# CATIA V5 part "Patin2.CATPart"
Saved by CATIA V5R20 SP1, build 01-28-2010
Part number: Patin2
Bounding box of the stored display mesh (mm): x 5 to 20, y -5.97 to 52.792, z 16.039 to 116.99
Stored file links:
  J:\ACHTUNG2\Patin2.CATPart
  J:\ACHTUNG2\cmilovidof.CATProduct
  J:\ACHTUNG\IAO non optimisé fini et qui marche à rendre\Patin2.CATPart
  J:\ACHTUNG2\Equerre6.CATPart
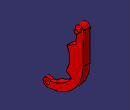
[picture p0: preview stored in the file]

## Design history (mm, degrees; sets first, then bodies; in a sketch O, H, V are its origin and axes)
External parameters (linked from other documents)
  External.diam_roue = 64 mm
Set1
  Plane1: linked copy from another document
  Line1 "Axe_Patin2Equerre6": linked copy from another document
  Line2 "Axe_Patin2Patin1": linked copy from another document
  Point1: linked copy from another document
  Plane2: linked copy from another document
Body1 (main body)
  Sketch1 on Plane2, origin (15, 0, 0), H (0, 1, 0), V (0, 0, 1)
    point P1 (0.5946, 67.9962)
    point P2 (0.5946, 67.9962)
    point P3 (4.3967, 26.0828)
    point P4 (4.3967, 26.0828)
    arc A1 centre (0.5946, 67.9962) radius 51.6165 from (2.1632, 16.4035) to (52.2068, 67.3289) ccw
    line L1 (52.2068, 67.3289) -> (52.7916, 112.5675)
    point P5 (52.2068, 67.3289)
    point P6 (52.2068, 67.3289)
    point P7 (52.7916, 112.5675)
    point P8 (52.7916, 112.5675)
    construction line L2 through (-0.3455, 4.2764) direction (0.0129, 0.9999)
    construction line L3 (0.5946, 67.9962) -> (0, 22)
    construction circle A2 centre (0.5946, 67.9962) radius 32
    arc A3 centre (0.5946, 67.9962) radius 32 from (27.2046, 50.2222) to (28.9219, 82.8813) ccw
    construction line L4 (27.2046, 50.2222) -> (0.5946, 67.9962)
    line L5 (27.2046, 50.2222) -> (35.5912, 44.6204)
    line L6 (28.9219, 82.8813) -> (41.8719, 89.6862)
    axis line L7 (0.5946, 67.9962) -> (28.9219, 82.8813)
    construction line L8 (42.1027, 107.5336) -> (41.4616, 57.9422)
    line L9 (42.1027, 107.5336) -> (41.8719, 89.6862)
    point P9 (35.5912, 44.6204)
    point P10 (35.5912, 44.6204)
    arc A4 centre (47, 111) radius 6 from (52.7916, 112.5675) to (42.1027, 107.5336) ccw
    arc A5 centre (0, 22) radius 6 from (4.3967, 26.0828) to (2.1632, 16.4035) ccw
    point P11 (0, 0)
    construction line L10 through (0, 0) direction (1, 0)
    point P13 (0, 22)
    construction arc A6 centre (0.5946, 67.9962) radius 42.0855 from (4.3967, 26.0828) to (41.4616, 57.9422) ccw
    arc A7 centre (0.5946, 67.9962) radius 42.0855 from (4.3967, 26.0828) to (35.5912, 44.6204) ccw
    reference projected point E1 (0, 22) from Line2
    reference projected point E2 (47, 111) from Line1
    angle L3 L5 = 57
    angle L5 L6 = 61.4613
    radius A3 = 32 {= 32*External.diam_roue /64}
    radius A4 = 6 {= 6*External.diam_roue /64}
    radius A5 = 6 {= 6*External.diam_roue /64}
    distance P13 P1 = 46 {= 46*External.diam_roue /64}
    distance L9 L1 = 10.623 {= 10.623*External.diam_roue /64}
    distance A7 A1 = 9.531 {= 9.531*External.diam_roue /64}
    coincidence: P2 P1, P4 P3, P6 P5, P8 P7, A3 A2, P10 P9
    tangency: L1 A1
    vertical: L3 L2, L1 L2, L9 L2
    parallelism: L5 L4, L7 L6, L8 L1
    concentricity: E1 A5, E2 A4
  Pad1: profile Sketch1, direction (-1, 0, 0), length 10
  Sketch2 on start face of Pad1, origin (15, 0, 0), H (0, 1, 0), V (0, 0, 1)
    circle A1 centre (47, 111) radius 3
    reference projected arc E1 centre (47, 111) radius 6 from (52.7916, 112.5675) to (42.1027, 107.5336) ccw from edge [face of Pad1 from Sketch1.A4 | start face of Pad1]
    radius A1 = 3 {= 3*External.diam_roue /64}
    concentricity: E1 A1
  Pad2: profile Sketch2, direction (1, 0, 0), length 5
  Sketch3 on end face of Pad1, origin (5, 0, 0), H (0, -1, 0), V (0, 0, 1)
    line L1 (-10, 32) -> (10, 32)
    line L2 (10, 32) -> (10, 12)
    line L3 (10, 12) -> (-10, 12)
    line L4 (-10, 12) -> (-10, 32)
    reference projected point E1 (0, 22) from Point1
    reference projected point E2 (0, 22) from Point1
    length L2 = 20
    length L1 = 20
    distance E1 L2 = 10
    distance L3 E2 = 10
    horizontal: L1 H, L3 H
    vertical: L2 V, L4 V
  Pocket1: profile Sketch3, direction (1, 0, 0), length 5
  Sketch4 on end face of Pocket1, origin (10, -0.7241, 17.9456), H (0, 1, 0), V (0, 0, -1)
    point P1 (0.7241, -4.0544)
    reference projected arc E1 centre (0.7241, -4.0544) radius 6 from (2.8873, 1.542) to (5.1208, -8.1372) ccw from edge [face of Pad1 from Sketch1.A5 | end face of Pocket1]
    concentricity: E1 P1
  Hole1: placed by Sketch4, at (10, 0, 22) direction (1, 0, 0), diameter 6 {= 6*External.diam_roue /64}, through (limit type 6)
